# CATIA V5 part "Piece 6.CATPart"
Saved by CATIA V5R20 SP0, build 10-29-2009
Part number: Piece 6
Bounding box of the stored display mesh (mm): x -20 to 30, y -112.72 to 699, z -207.007 to 19.46
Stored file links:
  C:\Users\Lambert\Desktop\IAO\Piece 6.CATPart
  C:\Users\Lambert\Desktop\IAO\Ass_Mon_IAO.CATProduct
  C:\Users\Lambert\Desktop\IAO\Piece 3.CATPart
  C:\Users\Lambert\Desktop\IAO\Piece 1.CATPart
  C:\Users\Lambert\Desktop\IAO\Piece 2.CATPart
  C:\Users\Lambert\Desktop\IAO\Piece3.CATPart
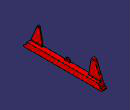
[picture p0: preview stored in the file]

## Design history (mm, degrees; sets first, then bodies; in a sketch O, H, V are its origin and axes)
Set1
  Point1 "A": linked copy from another document
  DatumPoint1 "D": linked copy from another document
  Point2 "G": linked copy from another document
  DatumCurve1: linked copy from another document
  Line1 "Bielle 3": linked copy from another document
  DatumCurve2: linked copy from another document
  DatumCurve3: linked copy from another document
  DatumPoint2 "C": linked copy from another document
  DatumCurve4 to DatumCurve7: linked copy from another document
Body1 (main body)
  Sketch1 on yz-plane, origin (0, 0, 0), H (0, 1, 0), V (0, 0, 1)
    construction line L1 (0, -179.146) -> (0, 0)
    point P2 (0, 0)
    arc A1 centre (0, 0) radius 13.6659 from (-12.6148, 5.2559) to (13.4583, 2.3731) cw
    reference projected point E1 (0, 0) from Point1
    construction line L2 (301.0345, -157.0625) -> (301.0345, -135.197)
    point P6 (301.0345, -135.197)
    line L3 (276.0345, -150.8482) -> (276.0345, -150.8482)
    line L4 (328.4378, -150.8482) -> (328.4378, -150.8482)
    point P7 (276.0345, -150.8482)
    point P8 (276.0345, -150.8482)
    point P9 (328.4378, -150.8482)
    point P10 (328.4378, -150.8482)
    reference projected point E2 (301.0345, -135.197) from DatumPoint1
    construction line L5 (580, -163.7256) -> (580, 0)
    point P12 (580, 0)
    arc A2 centre (580, 0) radius 19.462 from (560.8336, 3.3795) to (597.9651, 7.4851) cw
    reference projected point E3 (580, 0) from Point2
    axis line L6 (-46.4882, -150.8482) -> (704.01, -150.8482)
    line L7 (-112.7203, -207.0075) -> (699.0002, -207.0075)
    line L8 (560.8336, 3.3795) -> (533.6391, -150.8482)
    point P19 (533.6391, -150.8482)
    line L9 (13.4583, 2.3731) -> (40.4754, -150.8482)
    point P20 (40.4754, -150.8482)
    line L10 (40.4754, -150.8482) -> (276.0345, -150.8482)
    point P21 (40.4754, -150.8482)
    line L11 (328.4378, -150.8482) -> (533.6391, -150.8482)
    point P22 (533.6391, -150.8482)
    line L12 (-12.6148, 5.2559) -> (-92.7203, -187.0075)
    point P23 (-92.7203, -187.0075)
    line L13 (-92.7203, -187.0075) -> (-112.7203, -187.0075)
    point P24 (-112.7203, -187.0075)
    line L14 (-112.7203, -187.0075) -> (-112.7203, -207.0075)
    line L15 (597.9651, 7.4851) -> (679.0002, -187.0075)
    point P25 (679.0002, -187.0075)
    line L16 (679.0002, -187.0075) -> (699.0002, -187.0075)
    point P26 (699.0002, -187.0075)
    line L17 (699.0002, -187.0075) -> (699.0002, -207.0075)
    arc A3 centre (302.2362, -149.4105) radius 26.2411 from (276.0345, -150.8482) to (328.4378, -150.8482) cw
    point P28 (276.0345, -150.8482)
    point P29 (328.4378, -150.8482)
    distance L2 L3 = 25
    angle L12 L1 = 22.6188
    angle L15 L5 = 22.619
    distance P23 P24 = 20
    distance P26 P25 = 20
    angle L1 L9 = 10
    angle L5 L8 = 10
    distance L16 L7 = 20
    distance L13 L7 = 20
    vertical: L1 V, L2 V, L5 V, L14 V, L17 V
    coincidence: P2 E1, P6 E2, P12 E3, P10 L6, P7 L6, P19 L6, P20 L6, P21 L9, L10 P8, P19 P22, P9 P10, A3 P9, A3 P7, P28 L10, P29 P9
    parallelism: L3 L4, L16 L13
    horizontal: L6 H, L7 H, L10 H, L11 H, L13 H, L16 H
    tangency: L8 A2, L9 A1, L12 A1, L15 A2
  Pad1: profile Sketch1, direction (-1, 0, 0), length -30, opposite side length -20
  Sketch2 on face of Pad1 from Sketch1.L10, origin (0, 0, -150.8482), H (1, 0, 0), V (0, 1, 0)
    line L1 (-10, 63.4843) -> (60.3578, 63.4843)
    line L2 (60.3578, 63.4843) -> (60.3578, -104.8095)
    line L3 (60.3578, -104.8095) -> (-10, -104.8095)
    line L4 (-10, -104.8095) -> (-10, 63.4843)
    reference projected line E1 (-10, -39.6077) -> (-10, -62) from edge of DatumCurve5
    horizontal: L1 H, L3 H
    vertical: L2 V, L4 V
    coincidence: L4 E1
  Pocket1: profile Sketch2, direction (0, 0, 1), through (limit type 6)
  Sketch3 on face of Pocket1, origin (0, 0, -150.8482), H (1, 0, 0), V (0, 1, 0)
    line L1 (-10, 351.6689) -> (65.1584, 351.6689)
    line L2 (65.1584, 351.6689) -> (65.1584, 194.4955)
    line L3 (65.1584, 194.4955) -> (-10, 194.4955)
    line L4 (-10, 194.4955) -> (-10, 351.6689)
    reference projected line E1 (-10, 270.8482) -> (-10, 247.0188) from edge of DatumCurve6
    horizontal: L1 H, L3 H
    vertical: L2 V, L4 V
    coincidence: L4 E1
  Pocket2: profile Sketch3, direction (0, 0, 1), through (limit type 6)
  Sketch4 on face of Pocket2, origin (0, 0, -150.8482), H (1, 0, 0), V (0, 1, 0)
    line L1 (0, 700.8736) -> (93.6099, 700.8736)
    line L2 (93.6099, 700.8736) -> (93.6099, 518.2243)
    line L3 (93.6099, 518.2243) -> (0, 518.2243)
    line L4 (0, 518.2243) -> (0, 700.8736)
    reference projected line E1 (0, 579.6742) -> (0, 269.7885) from edge of DatumCurve7
    horizontal: L1 H, L3 H
    vertical: L2 V, L4 V
    coincidence: L4 E1
  Pocket3: profile Sketch4, direction (0, 0, 1), through (limit type 6)
  Fillet1: radius 5, on edge [face of Pocket1 from Sketch2.L4 | face of Pocket3]
  Fillet2: radius 5, on edge [face of Pad1 from Sketch1.L9 | face of Pocket3]
  Fillet3: radius 10, on edge [face of Pad1 from Sketch1.L13 | face of Pad1 from Sketch1.L12]
  Fillet4: radius 10, on edge [face of Pad1 from Sketch1.L14 | face of Pad1 from Sketch1.L13]
  Fillet5: radius 5, on edge [face of Pocket3 | face of Pad1 from Sketch1.A3]
  Fillet6: radius 5, on edge [face of Pocket2 from Sketch3.L4 | face of Pocket3]
  Fillet7: radius 5, on edge [face of Pad1 from Sketch1.A3 | face of Pocket3]
  Fillet8: radius 5, on edge [face of Pocket3 from Sketch4.L4 | face of Pocket3]
  Fillet9: radius 5, on edge [face of Pad1 from Sketch1.L8 | face of Pocket3]
  Fillet10: radius 10, on edge [face of Pad1 from Sketch1.L15 | face of Pad1 from Sketch1.L16]
  Fillet11: radius 10, on edge [face of Pad1 from Sketch1.L16 | face of Pad1 from Sketch1.L17]
  Sketch5 on face of Pocket2 from Sketch3.L4, origin (-10, 320.1724, -136.9106), H (0, 1, 0), V (0, 0, 1)
    point P1 (-19.1379, 1.7135)
    reference projected point E1 (-19.1379, 1.7135) from DatumPoint1
    coincidence: P1 E1
  Hole1: placed by Sketch5, at (-10, 301.0345, -135.197) direction (-1, 0, 0), diameter 10, through (limit type 6)
  Sketch6 on face of Pocket1 from Sketch2.L4, origin (-10, 14.6543, -36.4276), H (0, 1, 0), V (0, 0, 1)
    point P1 (-14.6543, 36.4276)
    reference projected point E1 (-14.6543, 36.4276) from Point1
    coincidence: P1 E1
  Hole2: placed by Sketch6, at (-10, 0, 0) direction (-1, 0, 0), diameter 10, through (limit type 6)
  Sketch7 on face of Pocket3 from Sketch4.L4, origin (0, 580.0137, -70.8101), H (0, 1, 0), V (0, 0, 1)
    point P1 (-0.0137, 70.8101)
    reference projected point E1 (-0.0137, 70.8101) from Point2
    coincidence: P1 E1
  Hole3: placed by Sketch7, at (0, 580, 0) direction (-1, 0, 0), diameter 10, through (limit type 6)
